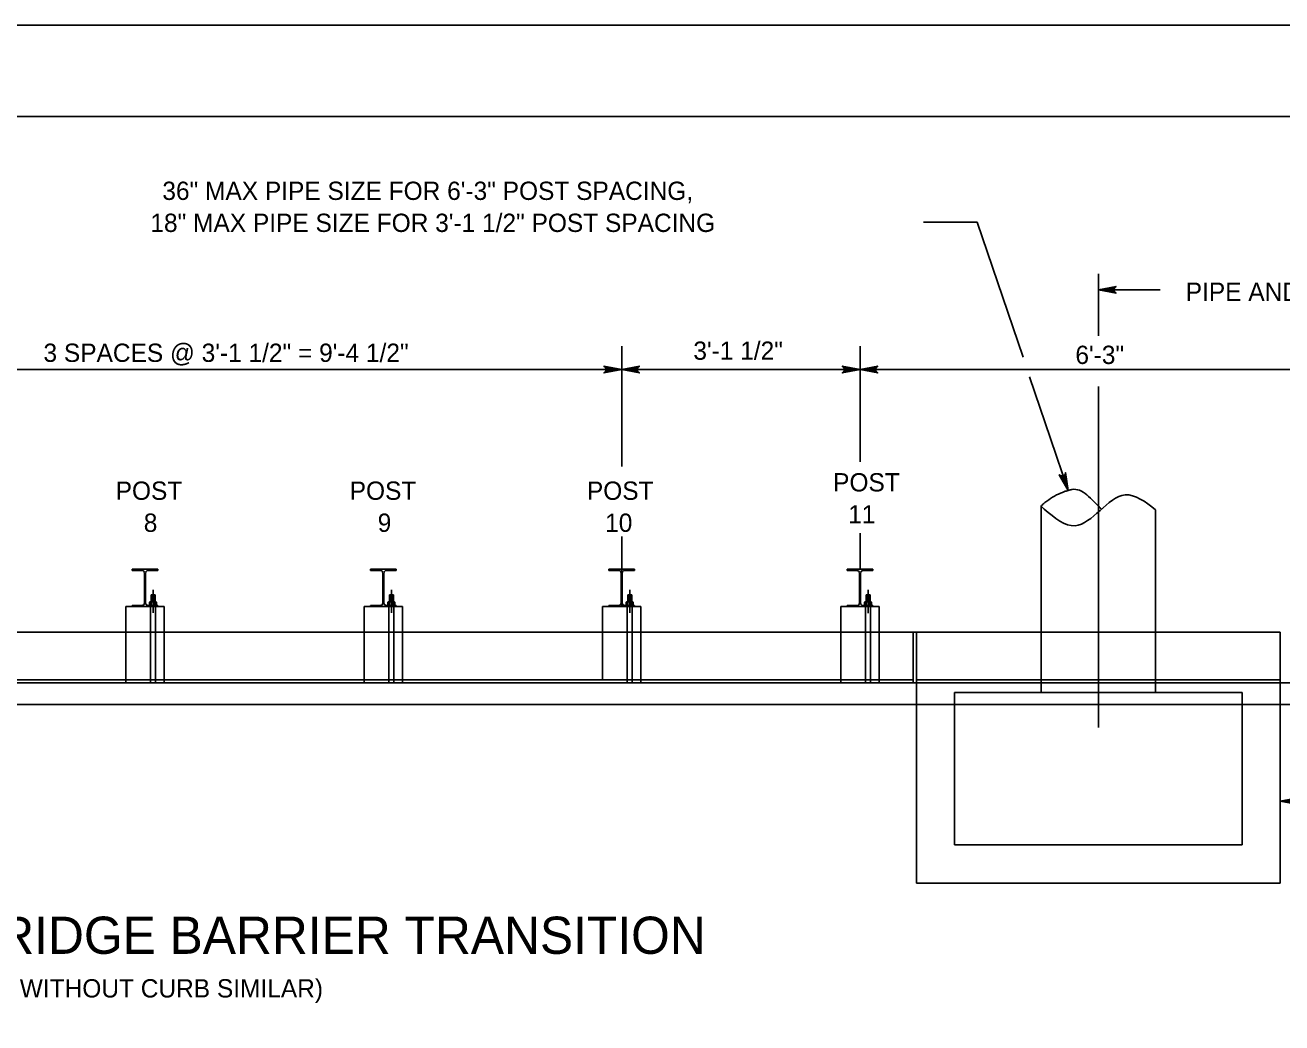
# Model space of a CAD drawing. Extents: x 632007860 to 635435983, y 295418622 to 297794622.
# Drawn here: x 632276713 to 632482682, y 297631068 to 297794622 of the extents above; entities that cross this region are included whole.
import ezdxf

# ---------------------------------------------------------------- set-up
doc = ezdxf.new("R2010")
doc.units = 0
for name, color, linetype in [('1', 7, 'Continuous'), ('PLT-BNDY', 7, 'Continuous'), ('S-ABUT', 7, 'Continuous'), ('S-DETL-DIMS', 7, 'Continuous'), ('S-DETL-T120', 7, 'Continuous'), ('S-DETL-T175', 7, 'Continuous'), ('S-MISC-CNTR-WT01', 7, 'Continuous'), ('S-STEL', 7, 'Continuous')]:
    doc.layers.add(name, color=color, linetype=linetype)

msp = doc.modelspace()

# ---------------------------------------------------------------- linework, layer by layer
at = {"layer": '1'}
msp.add_lwpolyline([(632833860, 297215622), (632833860, 297779622), (632047860, 297779622), (632047860, 297215622), (632833860, 297215622), (632833860, 297241981), (632633860, 297241981), (632633860, 297306659), (632833860, 297306659), (632833860, 297335622), (632633860, 297335622), (632633860, 297215622), (632712661, 297215622), (632712661, 297241981), (632712661, 297215622), (632789661, 297215622), (632789661, 297241981), (632789661, 297229665), (632833860, 297229665)], dxfattribs=at)
at = {"layer": 'PLT-BNDY'}
msp.add_lwpolyline([(632007860, 297794622), (632848860, 297794622), (632848860, 297200622), (632007860, 297200622)], close=True, dxfattribs=at)
at = {"layer": 'S-ABUT'}
for p, q in [((632260432, 297695131), (632293235, 297695131)), ((632293235, 297695131), (632299492, 297695131)), ((632299492, 297695131), (632332295, 297695131)), ((632332295, 297695131), (632338553, 297695131)), ((632338553, 297695131), (632371356, 297695131)), ((632371356, 297695131), (632377613, 297695131)), ((632377613, 297695131), (632410416, 297695131)), ((632410416, 297695131), (632416674, 297695131)), ((632416674, 297695131), (632482422, 297695131)), ((632422268, 297686797), (632422268, 297695127)), ((632422790, 297653983), (632422790, 297695127)), ((632423350, 297695127), (632482422, 297695127)), ((632482422, 297695131), (632482422, 297653983)), ((632293235, 297687315), (632260432, 297687315)), ((632293235, 297687315), (632299514, 297687315)), ((632332295, 297687315), (632299492, 297687315)), ((632332295, 297687315), (632338574, 297687315)), ((632371356, 297687315), (632338553, 297687315)), ((632371356, 297687315), (632377635, 297687315)), ((632410416, 297687315), (632377613, 297687315)), ((632410416, 297687315), (632416695, 297687315)), ((632422268, 297687315), (632416674, 297687315)), ((632482422, 297687315), (632422790, 297687315)), ((632429039, 297685231), (632476172, 297685231)), ((632429039, 297683412), (632429039, 297685231)), ((632429039, 297660232), (632429039, 297683412)), ((632476172, 297685231), (632476172, 297683412)), ((632476172, 297683412), (632476172, 297660232)), ((632476172, 297660232), (632429039, 297660232)), ((632482422, 297653983), (632422790, 297653983))]:
    msp.add_line(p, q, dxfattribs=at)
at = {"layer": 'S-DETL-DIMS'}
for p, q in [((632432763, 297762344), (632423932, 297762344)), ((632440261, 297740182), (632432763, 297762344)), ((632462746, 297751233), (632452606, 297751233)), ((632413545, 297738146), (632257303, 297738146)), ((632491666, 297738146), (632413545, 297738146)), ((632444759, 297726885), (632441341, 297736988)), ((632447649, 297718341), (632444759, 297726885)), ((632482422, 297667397), (632496719, 297667397))]:
    msp.add_line(p, q, dxfattribs=at)
for points in [[(632452606, 297751233), (632455518, 297751779), (632455406, 297751701), (632455294, 297751623), (632455236, 297751526), (632455178, 297751428), (632455161, 297751330), (632455144, 297751233), (632455161, 297751135), (632455178, 297751037), (632455236, 297750940), (632455294, 297750842), (632455406, 297750764), (632455518, 297750687), (632452606, 297751233), (632455406, 297750764), (632455294, 297750842), (632452606, 297751233), (632455236, 297750940), (632455178, 297751037), (632452606, 297751233), (632455161, 297751135), (632455144, 297751233), (632452606, 297751233), (632455161, 297751330), (632455178, 297751428), (632452606, 297751233), (632455236, 297751526), (632455294, 297751623), (632452606, 297751233), (632455406, 297751701)], [(632374484, 297738146), (632371572, 297737600), (632371796, 297737755), (632371912, 297737951), (632371946, 297738146), (632371912, 297738341), (632371796, 297738537), (632371572, 297738692), (632374484, 297738146), (632371796, 297738537), (632371912, 297738341), (632374484, 297738146), (632371946, 297738146), (632371912, 297737951), (632374484, 297738146), (632371796, 297737755)], [(632374484, 297738146), (632377397, 297738692), (632377173, 297738537), (632377057, 297738341), (632377023, 297738146), (632377057, 297737951), (632377173, 297737755), (632377397, 297737600), (632374484, 297738146), (632377173, 297737755), (632377057, 297737951), (632374484, 297738146), (632377023, 297738146), (632377057, 297738341), (632374484, 297738146), (632377173, 297738537)], [(632413545, 297738146), (632410632, 297737600), (632410857, 297737755), (632410973, 297737951), (632411006, 297738146), (632410973, 297738341), (632410857, 297738537), (632410632, 297738692), (632413545, 297738146), (632410857, 297738537), (632410973, 297738341), (632413545, 297738146), (632411006, 297738146), (632410973, 297737951), (632413545, 297738146), (632410857, 297737755)], [(632413545, 297738146), (632416458, 297738692), (632416233, 297738537), (632416117, 297738341), (632416084, 297738146), (632416117, 297737951), (632416233, 297737755), (632416458, 297737600), (632413545, 297738146), (632416233, 297737755), (632416117, 297737951), (632413545, 297738146), (632416084, 297738146), (632416117, 297738341), (632413545, 297738146), (632416233, 297738537)], [(632447649, 297718341), (632446199, 297720925), (632446308, 297720844), (632446418, 297720763), (632446529, 297720739), (632446640, 297720716), (632446738, 297720731), (632446836, 297720746), (632446923, 297720794), (632447010, 297720841), (632447084, 297720927), (632447158, 297721013), (632447195, 297721144), (632447233, 297721275), (632447649, 297718341), (632447195, 297721144), (632447158, 297721013), (632447649, 297718341), (632447084, 297720927), (632447010, 297720841), (632447649, 297718341), (632446923, 297720794), (632446836, 297720746), (632447649, 297718341), (632446738, 297720731), (632446640, 297720716), (632447649, 297718341), (632446529, 297720739), (632446418, 297720763), (632447649, 297718341), (632446308, 297720844)], [(632482422, 297667397), (632485334, 297667943)], [(632485110, 297667787), (632482422, 297667397), (632485222, 297667865)], [(632484994, 297667592), (632482422, 297667397), (632485052, 297667689)], [(632484960, 297667397), (632482422, 297667397), (632484977, 297667494)], [(632485334, 297666850), (632482422, 297667397), (632485222, 297666928)], [(632485110, 297667006), (632482422, 297667397), (632485052, 297667104)], [(632484994, 297667201), (632482422, 297667397), (632484977, 297667299)]]:
    msp.add_lwpolyline(points, dxfattribs=at)
at = {"layer": 'S-MISC-CNTR-WT01'}
for p, q in [((632452606, 297743699), (632452606, 297753852)), ((632374484, 297722248), (632374484, 297742000)), ((632413545, 297723020), (632413545, 297742000)), ((632452606, 297679513), (632452606, 297735393)), ((632374484, 297699296), (632374484, 297710817)), ((632413545, 297705414), (632413545, 297711364)), ((632297674, 297698256), (632297674, 297702079)), ((632336735, 297698257), (632336735, 297702079)), ((632375795, 297698256), (632375795, 297702079)), ((632414856, 297698254), (632414856, 297702077))]:
    msp.add_line(p, q, dxfattribs=at)
at = {"layer": 'S-STEL'}
for p, q in [((632443231, 297695127), (632443231, 297715792)), ((632443735, 297715262), (632443231, 297715792)), ((632461980, 297695127), (632461980, 297715191)), ((632294276, 297705415), (632298451, 297705415)), ((632294276, 297705415), (632294276, 297705220)), ((632294276, 297705220), (632295875, 297705220)), ((632296266, 297704796), (632296266, 297699850)), ((632296461, 297704796), (632296461, 297699850)), ((632296852, 297705220), (632298451, 297705220)), ((632298451, 297705220), (632298451, 297705415)), ((632333336, 297705416), (632337512, 297705416)), ((632333336, 297705416), (632333336, 297705221)), ((632333336, 297705221), (632334935, 297705221)), ((632335326, 297704796), (632335326, 297699851)), ((632335521, 297704796), (632335521, 297699851)), ((632335913, 297705221), (632337512, 297705221)), ((632337512, 297705221), (632337512, 297705416)), ((632372397, 297705416), (632376572, 297705416)), ((632372397, 297705416), (632372397, 297705221)), ((632372397, 297705221), (632373996, 297705221)), ((632374387, 297704861), (632374387, 297699850)), ((632374582, 297704861), (632374582, 297699850)), ((632374973, 297705221), (632376572, 297705221)), ((632376572, 297705221), (632376572, 297705416)), ((632411457, 297705414), (632415633, 297705414)), ((632411457, 297705414), (632411457, 297705219)), ((632411457, 297705219), (632413056, 297705219)), ((632413448, 297704794), (632413448, 297699849)), ((632413643, 297704794), (632413643, 297699849)), ((632414034, 297705219), (632415633, 297705219)), ((632415633, 297705219), (632415633, 297705414)), ((632297092, 297700025), (632297208, 297700092)), ((632297092, 297699558), (632297092, 297700025)), ((632298140, 297700092), (632297208, 297700092)), ((632297343, 297700092), (632297343, 297701238)), ((632298015, 297701238), (632297343, 297701238)), ((632298015, 297701081), (632297343, 297701081)), ((632298015, 297700924), (632297343, 297700924)), ((632298015, 297700767), (632297343, 297700767)), ((632298015, 297700609), (632297343, 297700609)), ((632298015, 297700452), (632297343, 297700452)), ((632298015, 297700295), (632297343, 297700295)), ((632298015, 297700138), (632297343, 297700138)), ((632297383, 297699558), (632297383, 297700025)), ((632297912, 297701159), (632297453, 297701159)), ((632297912, 297701002), (632297453, 297701002)), ((632297912, 297700845), (632297453, 297700845)), ((632297912, 297700688), (632297453, 297700688)), ((632297912, 297700531), (632297453, 297700531)), ((632297912, 297700374), (632297453, 297700374)), ((632297912, 297700217), (632297453, 297700217)), ((632297965, 297699558), (632297965, 297700025)), ((632298015, 297700092), (632298015, 297701238)), ((632298257, 297700025), (632298140, 297700092)), ((632298257, 297699558), (632298257, 297700025)), ((632336152, 297700025), (632336269, 297700093)), ((632336152, 297699559), (632336152, 297700025)), ((632337201, 297700093), (632336269, 297700093)), ((632336404, 297700093), (632336404, 297701239)), ((632337076, 297701239), (632336404, 297701239)), ((632337076, 297701082), (632336404, 297701082)), ((632337076, 297700924), (632336404, 297700924)), ((632337076, 297700767), (632336404, 297700767)), ((632337076, 297700610), (632336404, 297700610)), ((632337076, 297700453), (632336404, 297700453)), ((632337076, 297700296), (632336404, 297700296)), ((632337076, 297700139), (632336404, 297700139)), ((632336444, 297699559), (632336444, 297700025)), ((632336973, 297701160), (632336513, 297701160)), ((632336973, 297701003), (632336513, 297701003)), ((632336973, 297700846), (632336513, 297700846)), ((632336973, 297700689), (632336513, 297700689)), ((632336973, 297700532), (632336513, 297700532)), ((632336973, 297700375), (632336513, 297700375)), ((632336973, 297700217), (632336513, 297700217)), ((632337026, 297699559), (632337026, 297700025)), ((632337076, 297700093), (632337076, 297701239)), ((632337317, 297700025), (632337201, 297700093)), ((632337317, 297699559), (632337317, 297700025)), ((632375213, 297700025), (632375329, 297700092)), ((632375213, 297699558), (632375213, 297700025)), ((632376261, 297700092), (632375329, 297700092)), ((632375464, 297700092), (632375464, 297701238)), ((632376136, 297701238), (632375464, 297701238)), ((632376136, 297701081), (632375464, 297701081)), ((632376136, 297700924), (632375464, 297700924)), ((632376136, 297700767), (632375464, 297700767)), ((632376136, 297700609), (632375464, 297700609)), ((632376136, 297700452), (632375464, 297700452)), ((632376136, 297700295), (632375464, 297700295)), ((632376136, 297700138), (632375464, 297700138)), ((632375504, 297699558), (632375504, 297700025)), ((632376033, 297701159), (632375574, 297701159)), ((632376033, 297701002), (632375574, 297701002)), ((632376033, 297700845), (632375574, 297700845)), ((632376033, 297700688), (632375574, 297700688)), ((632376033, 297700531), (632375574, 297700531)), ((632376033, 297700374), (632375574, 297700374)), ((632376033, 297700217), (632375574, 297700217)), ((632376087, 297699558), (632376087, 297700025)), ((632376136, 297700092), (632376136, 297701238)), ((632376378, 297700025), (632376261, 297700092)), ((632376378, 297699558), (632376378, 297700025)), ((632414274, 297700023), (632414390, 297700090)), ((632414274, 297699556), (632414274, 297700023)), ((632415322, 297700090), (632414390, 297700090)), ((632414525, 297700090), (632414525, 297701236)), ((632415197, 297701236), (632414525, 297701236)), ((632415197, 297701079), (632414525, 297701079)), ((632415197, 297700922), (632414525, 297700922)), ((632415197, 297700765), (632414525, 297700765)), ((632415197, 297700608), (632414525, 297700608)), ((632415197, 297700451), (632414525, 297700451)), ((632415197, 297700294), (632414525, 297700294)), ((632415197, 297700136), (632414525, 297700136)), ((632414565, 297699556), (632414565, 297700023)), ((632415094, 297701158), (632414634, 297701158)), ((632415094, 297701001), (632414634, 297701001)), ((632415094, 297700844), (632414634, 297700844)), ((632415094, 297700686), (632414634, 297700686)), ((632415094, 297700529), (632414634, 297700529)), ((632415094, 297700372), (632414634, 297700372)), ((632415094, 297700215), (632414634, 297700215)), ((632415147, 297699556), (632415147, 297700023)), ((632415197, 297700090), (632415197, 297701236)), ((632415438, 297700023), (632415322, 297700090)), ((632415438, 297699556), (632415438, 297700023)), ((632293235, 297699296), (632299492, 297699296)), ((632293235, 297699296), (632293235, 297686797)), ((632294276, 297699491), (632294276, 297699296)), ((632294276, 297699491), (632295875, 297699491)), ((632294276, 297699296), (632298451, 297699296)), ((632296852, 297699491), (632298451, 297699491)), ((632297092, 297699558), (632297208, 297699491)), ((632298140, 297699491), (632297208, 297699491)), ((632297284, 297699491), (632297284, 297686732)), ((632298065, 297699491), (632298065, 297686732)), ((632298257, 297699558), (632298140, 297699491)), ((632298451, 297699296), (632298451, 297699491)), ((632299492, 297699296), (632299492, 297686797)), ((632332295, 297699297), (632338553, 297699297)), ((632332295, 297699297), (632332295, 297686798)), ((632333336, 297699492), (632333336, 297699297)), ((632333336, 297699492), (632334935, 297699492)), ((632333336, 297699297), (632337512, 297699297)), ((632335913, 297699492), (632337512, 297699492)), ((632336152, 297699559), (632336269, 297699492)), ((632337201, 297699492), (632336269, 297699492)), ((632336344, 297699492), (632336344, 297686733)), ((632337125, 297699492), (632337125, 297686733)), ((632337317, 297699559), (632337201, 297699492)), ((632337512, 297699297), (632337512, 297699492)), ((632338553, 297699297), (632338553, 297686798)), ((632371356, 297699296), (632377613, 297699296)), ((632371356, 297699296), (632371356, 297687315)), ((632372397, 297699491), (632372397, 297699296)), ((632372397, 297699491), (632373996, 297699491)), ((632372397, 297699296), (632376572, 297699296)), ((632374973, 297699491), (632376572, 297699491)), ((632375213, 297699558), (632375329, 297699491)), ((632376261, 297699491), (632375329, 297699491)), ((632375405, 297699491), (632375405, 297686732)), ((632376186, 297699491), (632376186, 297686732)), ((632376378, 297699558), (632376261, 297699491)), ((632376572, 297699296), (632376572, 297699491)), ((632377613, 297699296), (632377613, 297686797)), ((632410416, 297699294), (632416674, 297699294)), ((632410416, 297699294), (632410416, 297686795)), ((632411457, 297699489), (632411457, 297699294)), ((632411457, 297699489), (632413056, 297699489)), ((632411457, 297699294), (632415633, 297699294)), ((632414034, 297699489), (632415633, 297699489)), ((632414274, 297699556), (632414390, 297699489)), ((632415322, 297699489), (632414390, 297699489)), ((632414465, 297699489), (632414465, 297686731)), ((632415246, 297699489), (632415246, 297686731)), ((632415438, 297699556), (632415322, 297699489)), ((632415633, 297699294), (632415633, 297699489)), ((632416674, 297699294), (632416674, 297686795)), ((632443231, 297685231), (632443231, 297695127)), ((632461980, 297685231), (632461980, 297695127)), ((632080107, 297686797), (632580147, 297686797)), ((632293235, 297686797), (632299492, 297686797)), ((632332295, 297686798), (632338553, 297686798)), ((632371356, 297686797), (632377613, 297686797)), ((632410416, 297686795), (632416674, 297686795)), ((632054741, 297683282), (632580147, 297683282))]:
    msp.add_line(p, q, dxfattribs=at)
for centre, start, end in [((632295890, 297704845), 2.38198, 92.38198), ((632296837, 297704845), 87.61802, 177.61802), ((632334951, 297704846), 2.38198, 92.38198), ((632335897, 297704846), 87.61802, 177.61802), ((632374011, 297704845), 2.38198, 92.38198), ((632374958, 297704845), 87.61802, 177.61802), ((632413072, 297704843), 2.38198, 92.38198), ((632414018, 297704843), 87.61802, 177.61802), ((632295890, 297699866), 267.61802, 357.61802), ((632296837, 297699866), 182.38198, 272.38198), ((632334951, 297699867), 267.61802, 357.61802), ((632335897, 297699867), 182.38198, 272.38198), ((632374011, 297699866), 267.61802, 357.61802), ((632374958, 297699866), 182.38198, 272.38198), ((632413072, 297699864), 267.61802, 357.61802), ((632414018, 297699864), 182.38198, 272.38198)]:
    msp.add_arc(centre, 376, start, end, dxfattribs=at)
for points in [[(632443231, 297715792), (632443381, 297715938), (632443532, 297716079), (632443839, 297716348), (632444464, 297716833), (632445746, 297717607), (632447035, 297718150), (632447670, 297718347), (632447982, 297718429), (632448137, 297718466), (632448291, 297718500), (632449500, 297718367), (632450705, 297717613), (632451909, 297716494), (632453112, 297715268)], [(632443735, 297715262), (632448795, 297712554), (632456991, 297717614), (632461980, 297715191)]]:
    msp.add_spline(points, degree=3, dxfattribs=at)
for points in [[(632297238, 297700092), (632297258, 297700089), (632297302, 297700083), (632297349, 297700053), (632297375, 297700031), (632297383, 297700025)], [(632297383, 297700025), (632297408, 297700035), (632297466, 297700058), (632297563, 297700086), (632297637, 297700090), (632297674, 297700092)], [(632297674, 297700092), (632297681, 297700092), (632297725, 297700091), (632297806, 297700080), (632297896, 297700053), (632297948, 297700032), (632297965, 297700025)], [(632297965, 297700025), (632297987, 297700042), (632298030, 297700076), (632298084, 297700092), (632298110, 297700092), (632298111, 297700092)], [(632336298, 297700093), (632336319, 297700090), (632336363, 297700084), (632336410, 297700053), (632336436, 297700032), (632336444, 297700025)], [(632336444, 297700025), (632336468, 297700035), (632336527, 297700059), (632336624, 297700086), (632336698, 297700091), (632336735, 297700093)], [(632336735, 297700093), (632336742, 297700093), (632336785, 297700092), (632336867, 297700081), (632336957, 297700054), (632337009, 297700033), (632337026, 297700025)], [(632337026, 297700025), (632337048, 297700043), (632337090, 297700076), (632337144, 297700093), (632337171, 297700093), (632337172, 297700093)], [(632375359, 297700092), (632375379, 297700089), (632375424, 297700083), (632375470, 297700053), (632375496, 297700031), (632375504, 297700025)], [(632375504, 297700025), (632375529, 297700035), (632375587, 297700058), (632375684, 297700086), (632375758, 297700090), (632375795, 297700092)], [(632375795, 297700092), (632375802, 297700092), (632375846, 297700091), (632375927, 297700080), (632376017, 297700053), (632376069, 297700032), (632376087, 297700025)], [(632376087, 297700025), (632376108, 297700042), (632376151, 297700076), (632376205, 297700092), (632376231, 297700092), (632376232, 297700092)], [(632414419, 297700090), (632414440, 297700088), (632414484, 297700082), (632414531, 297700051), (632414557, 297700030), (632414565, 297700023)], [(632414565, 297700023), (632414589, 297700033), (632414648, 297700057), (632414745, 297700084), (632414819, 297700088), (632414856, 297700090)], [(632414856, 297700090), (632414863, 297700090), (632414906, 297700090), (632414988, 297700079), (632415078, 297700052), (632415130, 297700030), (632415147, 297700023)], [(632415147, 297700023), (632415169, 297700041), (632415211, 297700074), (632415266, 297700090), (632415292, 297700090), (632415293, 297700090)], [(632297238, 297699491), (632297258, 297699494), (632297302, 297699499), (632297349, 297699530), (632297375, 297699551), (632297383, 297699558)], [(632297383, 297699558), (632297408, 297699548), (632297466, 297699524), (632297563, 297699497), (632297637, 297699493), (632297674, 297699491)], [(632297674, 297699491), (632297681, 297699491), (632297725, 297699491), (632297806, 297699502), (632297896, 297699529), (632297948, 297699551), (632297965, 297699558)], [(632297965, 297699558), (632297987, 297699541), (632298030, 297699507), (632298084, 297699491), (632298110, 297699491), (632298111, 297699491)], [(632336298, 297699492), (632336319, 297699494), (632336363, 297699500), (632336410, 297699531), (632336436, 297699552), (632336444, 297699559)], [(632336444, 297699559), (632336468, 297699549), (632336527, 297699525), (632336624, 297699498), (632336698, 297699494), (632336735, 297699492)], [(632336735, 297699492), (632336742, 297699492), (632336785, 297699492), (632336867, 297699503), (632336957, 297699530), (632337009, 297699552), (632337026, 297699559)], [(632337026, 297699559), (632337048, 297699541), (632337090, 297699508), (632337144, 297699492), (632337171, 297699492), (632337172, 297699492)], [(632375359, 297699491), (632375379, 297699494), (632375424, 297699499), (632375470, 297699530), (632375496, 297699552), (632375504, 297699558)], [(632375504, 297699558), (632375529, 297699548), (632375587, 297699524), (632375684, 297699497), (632375758, 297699493), (632375795, 297699491)], [(632375795, 297699491), (632375802, 297699491), (632375846, 297699491), (632375927, 297699502), (632376017, 297699529), (632376069, 297699551), (632376087, 297699558)], [(632376087, 297699558), (632376108, 297699541), (632376151, 297699507), (632376205, 297699491), (632376231, 297699491), (632376232, 297699491)], [(632414419, 297699489), (632414440, 297699492), (632414484, 297699498), (632414531, 297699528), (632414557, 297699550), (632414565, 297699556)], [(632414565, 297699556), (632414589, 297699546), (632414648, 297699523), (632414745, 297699496), (632414819, 297699491), (632414856, 297699489)], [(632414856, 297699489), (632414863, 297699489), (632414906, 297699490), (632414988, 297699501), (632415078, 297699528), (632415130, 297699549), (632415147, 297699556)], [(632415147, 297699556), (632415169, 297699539), (632415211, 297699505), (632415266, 297699489), (632415292, 297699489), (632415293, 297699489)]]:
    msp.add_open_spline(points, degree=3, dxfattribs=at)

# ---------------------------------------------------------------- texts
at = {"layer": 'S-DETL-T120'}
for s, height, p in [('36" MAX PIPE SIZE FOR 6\'-3" POST SPACING,', 2999.85, (632299201, 297765966)), ('18" MAX PIPE SIZE FOR 3\'-1 1/2" POST SPACING', 2999.85, (632297241, 297760717)), ('  PIPE AND INLET (CENTERED BETWEEN POSTS)', 2999.85, (632464698, 297749420)), ('3 SPACES @ 3\'-1 1/2" = 9\'-4 1/2"', 2999.85, (632279722, 297739416)), ('3\'-1 1/2"', 2999.8, (632386230, 297739759)), ('6\'-3"', 2999.8, (632448842, 297739076)), ('POST', 2999.8, (632409137, 297718181)), ('POST', 2999.8, (632291547, 297716807)), ('POST', 2999.8, (632329904, 297716807)), ('POST', 2999.8, (632368783, 297716807)), ('8', 3000, (632296153, 297711557)), ('9', 3000, (632334498, 297711557)), ('10', 2999.8, (632371771, 297711557)), ('11', 2999.8, (632411606, 297712931)), ('(WITH CURB AND INLET PLACEMENT, WITHOUT CURB SIMILAR)', 2999.91, (632201838, 297635230))]:
    msp.add_text(s, height=height, dxfattribs=at).set_placement(p)
at = {"layer": 'S-DETL-T175'}
msp.add_text('PLAN VIEW FOR THRIE-BEAM GUIDE RAIL TO BRIDGE BARRIER TRANSITION', height=6096, dxfattribs=at).set_placement((632086151, 297642384))

doc.saveas('drawing.dxf')
